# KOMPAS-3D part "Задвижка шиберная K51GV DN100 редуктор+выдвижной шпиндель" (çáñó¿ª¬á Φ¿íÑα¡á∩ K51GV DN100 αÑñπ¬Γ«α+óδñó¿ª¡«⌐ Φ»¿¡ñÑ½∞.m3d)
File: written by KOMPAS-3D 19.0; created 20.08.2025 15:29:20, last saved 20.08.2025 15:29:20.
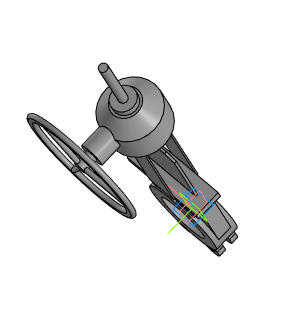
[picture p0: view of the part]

Document properties: Полное имя файла: Задвижка шиберная K51GV DN100 редуктор+выдвижной шпиндель.a3d

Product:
- Part/product: Задвижка шиберная K51GV DN100 редуктор+выдвижной шпиндель
    Масса: 20.5909

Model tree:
1. Операция без истории:1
